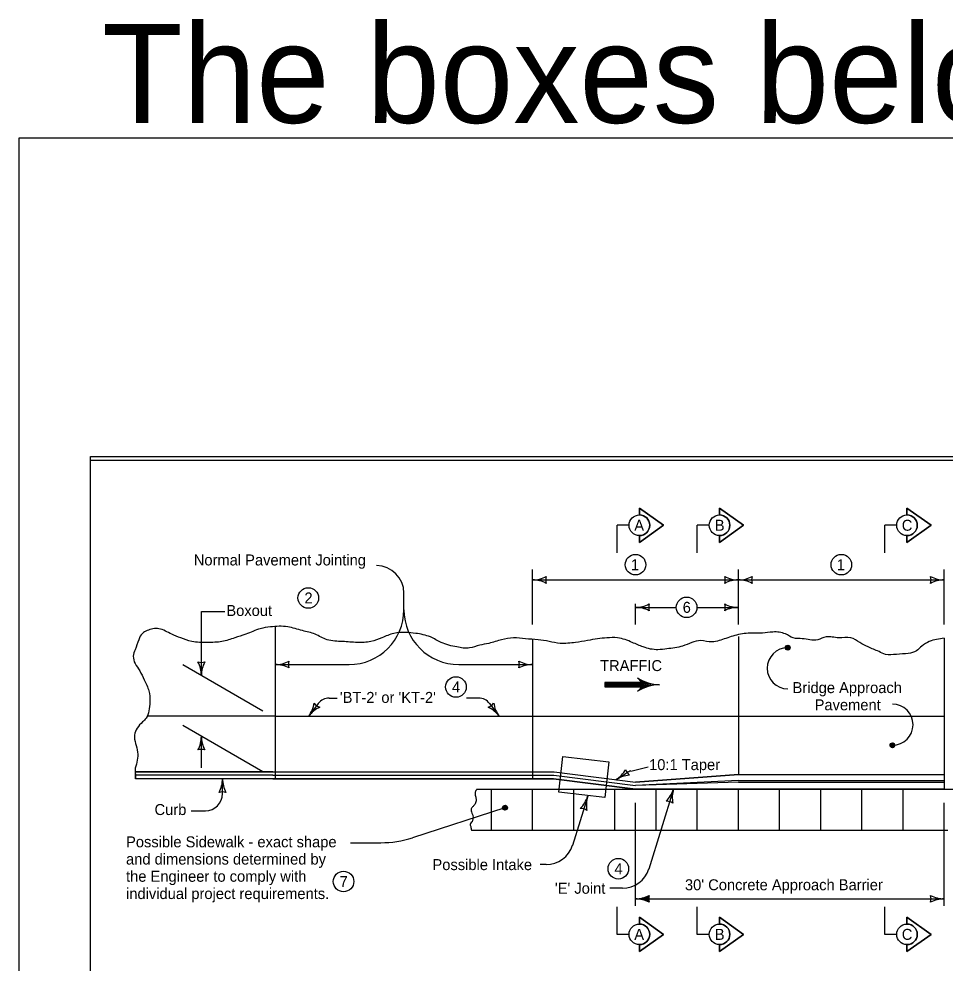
# Model space of a CAD drawing. Extents: x 10028 to 81668, y 6395 to 11634.
# Drawn here: x 10028 to 11378, y 9205 to 10582 of the extents above; entities that cross this region are included whole.
import ezdxf

# ---------------------------------------------------------------- set-up
doc = ezdxf.new("R2010")
doc.units = 0
for name, color, linetype in [('Default', 7, 'Continuous'), ('dsnCellElements', 7, 'Continuous'), ('dsnstdblockInterim', 7, 'Continuous'), ('dsnStdDimension', 7, 'Continuous'), ('dsnStdTextLabel', 7, 'Continuous'), ('ShtPlotIdentification', 7, 'Continuous')]:
    doc.layers.add(name, color=color, linetype=linetype)

msp = doc.modelspace()

# ---------------------------------------------------------------- linework, layer by layer
at = {"layer": 'Default'}
msp.add_lwpolyline([(10132.5, 9944), (13267.5, 9944), (13267.5, 7924), (10132.5, 7924)], close=True, dxfattribs=at)
msp.add_lwpolyline([(10132.5, 9944), (13267.5, 9944), (13267.5, 7924), (10132.5, 7924)], close=True, dxfattribs=at)
at = {"layer": 'dsnCellElements'}
for p, q in [((10932.4, 9828.9), (10932.4, 9828.9)), ((11049.2, 9828.9), (11049.2, 9828.9)), ((11322.4, 9828.9), (11322.4, 9828.9)), ((10198.2, 9474.3), (10197.8, 9484.3)), ((10197.8, 9484.3), (10398.2, 9484.3)), ((10398.2, 9474.3), (10198.2, 9474.3)), ((10926.7, 9469.3), (11076.7, 9480.5)), ((11076.7, 9480.5), (11376.7, 9480.5)), ((11376.7, 9480.5), (11376.7, 9459.2)), ((11376.7, 9459.2), (10926.7, 9459.2)), ((10932.4, 9232.4), (10932.4, 9232.4)), ((11049.2, 9232.4), (11049.2, 9232.4)), ((11322.4, 9232.4), (11322.4, 9232.4))]:
    msp.add_line(p, q, dxfattribs=at)
for points in [[(10932.4, 9828.9), (10932.4, 9818.9), (10967.4, 9843.9), (10932.4, 9868.9), (10932.4, 9858.9)], [(11049.2, 9828.9), (11049.2, 9818.9), (11084.2, 9843.9), (11049.2, 9868.9), (11049.2, 9858.9)], [(11322.4, 9828.9), (11322.4, 9818.9), (11357.4, 9843.9), (11322.4, 9868.9), (11322.4, 9858.9)], [(10398.2, 9484.3), (10808.3, 9484.3), (10926.7, 9469.3)], [(10926.7, 9459.2), (10807.2, 9474.3), (10398.2, 9474.3)], [(10932.4, 9232.4), (10932.4, 9222.4), (10967.4, 9247.4), (10932.4, 9272.4), (10932.4, 9262.4)], [(11049.2, 9232.4), (11049.2, 9222.4), (11084.2, 9247.4), (11049.2, 9272.4), (11049.2, 9262.4)], [(11322.4, 9232.4), (11322.4, 9222.4), (11357.4, 9247.4), (11322.4, 9272.4), (11322.4, 9262.4)]]:
    msp.add_lwpolyline(points, dxfattribs=at)
for centre in [(10932.4, 9843.9), (11049.2, 9843.9), (11322.4, 9843.9), (10932.4, 9247.4), (11049.2, 9247.4), (11322.4, 9247.4)]:
    msp.add_arc(centre, 15, 270.0001, 89.9999, dxfattribs=at)
at = {"layer": 'dsnstdblockInterim'}
for points in [[(10132.5, 9944), (13267.5, 9944), (13267.5, 7924), (10132.5, 7924)], [(10132.5, 9939), (13267.5, 9939), (13267.5, 7929), (10132.5, 7929)]]:
    msp.add_lwpolyline(points, close=True, dxfattribs=at)
at = {"layer": 'dsnStdDimension'}
msp.add_lwpolyline([(10028, 7824.5), (13372, 7824.5), (13372, 10408.5), (10028, 10408.5)], close=True, dxfattribs=at)
at = {"layer": 'ShtPlotIdentification'}
for p, q in [((10900, 9803.9), (10900, 9843.9)), ((10917.4, 9843.9), (10900, 9843.9)), ((11034.2, 9843.9), (11016.7, 9843.9)), ((11016.7, 9803.9), (11016.7, 9843.9)), ((11290, 9803.9), (11290, 9843.9)), ((11307.4, 9843.9), (11290, 9843.9)), ((10776.7, 9699.2), (10776.7, 9779.2)), ((11076.7, 9699.2), (11076.7, 9779.2)), ((11376.7, 9699.2), (11376.7, 9779.2)), ((10776.7, 9764.2), (11076.7, 9764.2)), ((11076.7, 9764.2), (11376.7, 9764.2)), ((10589.2, 9720.8), (10589.2, 9745)), ((10926.7, 9699.2), (10926.7, 9729.2)), ((10926.7, 9724.2), (10986.2, 9724.2)), ((11016.2, 9724.2), (11076.7, 9724.2)), ((10294, 9718.4), (10328.2, 9718.4)), ((10294, 9624.8), (10294, 9718.4)), ((10401.7, 9696.3), (10401.7, 9474.3)), ((11076.7, 9681.6), (11076.7, 9480.5)), ((11376.7, 9679.2), (11376.7, 9459.2)), ((10776.7, 9677.8), (10776.7, 9474.3)), ((10383.7, 9573), (10266.8, 9640.5)), ((10401.7, 9640.8), (10509.2, 9640.8)), ((10669.2, 9640.8), (10776.7, 9640.8)), ((10934.9, 9611.5), (10881.8, 9611.5)), ((10934.7, 9614.7), (10934.7, 9614.7)), ((10934.8, 9608.5), (10934.8, 9608.5)), ((10464.3, 9583.9), (10450.4, 9565.5)), ((10480.3, 9591.9), (10492, 9591.9)), ((10698.1, 9591.9), (10680.5, 9591.9)), ((10714.1, 9583.9), (10728, 9565.5)), ((10401.7, 9565.5), (10215.1, 9565.5)), ((10401.7, 9565.5), (10776.7, 9565.5)), ((10776.7, 9565.5), (11376.7, 9565.5)), ((10383.7, 9484.5), (10266.8, 9552)), ((10294, 9490), (10294, 9536.3)), ((10197.6, 9489.5), (10198.2, 9474.3)), ((10920, 9485.6), (10945.2, 9491.6)), ((10398.2, 9484.3), (10197.8, 9484.3)), ((10398.2, 9479.3), (10198, 9479.3)), ((10398.2, 9474.3), (10198.2, 9474.3)), ((10324.8, 9452.6), (10324.8, 9474.3)), ((10898.3, 9472.9), (10913.8, 9483)), ((11076.7, 9480.5), (10926.7, 9469.3)), ((11076.7, 9480.5), (11376.7, 9480.5)), ((10695.6, 9459.2), (11376.7, 9459.2)), ((10716.7, 9399.2), (10716.7, 9459.2)), ((10776.7, 9399.2), (10776.7, 9459.2)), ((10836.7, 9399.2), (10836.7, 9459.2)), ((10896.7, 9399.2), (10896.7, 9459.2)), ((11076.7, 9471.7), (10926.7, 9464.3)), ((11076.7, 9469.2), (10926.7, 9464.3)), ((10926.7, 9459.2), (11376.7, 9459.2)), ((10926.7, 9459.2), (11367.8, 9459.2)), ((10982.2, 9459.2), (10946, 9342.7)), ((10956.7, 9399.2), (10956.7, 9459.2)), ((11016.7, 9399.2), (11016.7, 9459.2)), ((11076.7, 9471.7), (11376.7, 9471.7)), ((11076.7, 9469.2), (11376.7, 9469.2)), ((11076.7, 9399.2), (11076.7, 9459.2)), ((11136.7, 9399.2), (11136.7, 9459.2)), ((11196.7, 9399.2), (11196.7, 9459.2)), ((11256.7, 9399.2), (11256.7, 9459.2)), ((11316.7, 9399.2), (11316.7, 9459.2)), ((11376.7, 9459.2), (11706.6, 9459.2)), ((10857, 9448.7), (10834.8, 9377.2)), ((10736.5, 9432), (10601.8, 9388.3)), ((10926.7, 9289.2), (10926.7, 9439.2)), ((11376.7, 9289.2), (11376.7, 9439.2)), ((10278.9, 9427.6), (10299.8, 9427.6)), ((10687.5, 9399.2), (11381.7, 9399.2)), ((10511.5, 9381), (10555.5, 9381)), ((10796.6, 9349.1), (10788, 9349.1)), ((10907.8, 9314.6), (10889.4, 9314.6)), ((10926.7, 9299.2), (11376.7, 9299.2)), ((10926.7, 9299.2), (10945.9, 9299.2)), ((10900, 9247.4), (10900, 9287.4)), ((11016.7, 9247.4), (11016.7, 9287.4)), ((11290, 9247.4), (11290, 9287.4)), ((10917.4, 9247.4), (10900, 9247.4)), ((11034.2, 9247.4), (11016.7, 9247.4)), ((11307.4, 9247.4), (11290, 9247.4))]:
    msp.add_line(p, q, dxfattribs=at)
for points in [[(10932.4, 9858.9), (10932.4, 9868.9), (10967.4, 9843.9), (10932.4, 9818.9), (10932.4, 9828.9)], [(11049.2, 9858.9), (11049.2, 9868.9), (11084.2, 9843.9), (11049.2, 9818.9), (11049.2, 9828.9)], [(11322.4, 9858.9), (11322.4, 9868.9), (11357.4, 9843.9), (11322.4, 9818.9), (11322.4, 9828.9)], [(11148.4, 9662.2), (11149.5, 9662.8), (11151.4, 9663.3), (11151.7, 9665.2), (11151.5, 9666.8), (11150.3, 9668.3), (11148.6, 9668.2), (11146.7, 9667.9), (11145.8, 9666.5), (11145.7, 9664.9), (11146.8, 9662.9), (11148.1, 9662.7), (11149.9, 9663.2), (11151.4, 9664.4), (11151.4, 9666.1), (11150.2, 9667.5), (11148.6, 9667.7), (11146.7, 9667.3), (11146.4, 9666.3), (11146.1, 9665), (11146.9, 9663.5), (11148.3, 9663.5), (11149.8, 9663.8), (11150.9, 9664.6), (11150.4, 9666.2), (11149.2, 9667.1), (11147.7, 9667.1), (11147.3, 9666.3), (11146.8, 9665.4), (11147.5, 9664.1), (11148.7, 9663.9), (11149.7, 9664.4), (11149.8, 9665.5), (11149.2, 9666.3), (11148.2, 9666.6), (11147.7, 9666.2), (11147.4, 9665.6), (11147.9, 9664.7), (11148.7, 9664.5), (11149.4, 9664.9), (11149.3, 9665.5), (11148.7, 9665.9), (11148, 9665.9), (11148, 9665.4), (11148.6, 9665.1)], [(10934.8, 9614.5), (10881.8, 9614.5), (10881.8, 9608.5), (10934.8, 9608.5), (10934.6, 9613.6), (10882.5, 9613.8), (10882.6, 9609), (10933.6, 9609.2), (10933.7, 9612.8), (10883.2, 9613), (10883.4, 9609.8), (10932.9, 9609.8), (10933.1, 9612.1), (10883.8, 9612.4), (10883.9, 9610.6), (10932.3, 9610.6)], [(10933.3, 9618.4), (10935.6, 9614.8), (10935.9, 9609.6), (10933.9, 9605), (10941.8, 9608.3), (10950.9, 9610.9), (10953.5, 9611.5), (10946.9, 9612.8), (10937.2, 9616.1), (10934.4, 9617.7), (10935.5, 9606.5), (10949.6, 9611.3), (10935.8, 9615.5), (10936.3, 9607.8), (10946, 9611.4), (10937.1, 9613.6), (10936.7, 9609.1), (10942.9, 9611.1), (10938.2, 9612.4), (10937.9, 9610.3), (10940.2, 9611)], [(11300.9, 9519.9), (11302.1, 9520.4), (11303.9, 9521), (11304.3, 9522.9), (11304, 9524.5), (11302.9, 9526), (11301.1, 9525.9), (11299.3, 9525.6), (11298.4, 9524.1), (11298.2, 9522.6), (11299.3, 9520.6), (11300.7, 9520.4), (11302.5, 9520.9), (11304, 9522), (11304, 9523.8), (11302.8, 9525.2), (11301.1, 9525.4), (11299.3, 9525), (11299, 9524), (11298.6, 9522.7), (11299.5, 9521.2), (11300.8, 9521.2), (11302.4, 9521.5), (11303.5, 9522.3), (11302.9, 9523.9), (11301.8, 9524.8), (11300.2, 9524.8), (11299.8, 9524), (11299.4, 9523), (11300.1, 9521.8), (11301.2, 9521.6), (11302.3, 9522.1), (11302.3, 9523.2), (11301.8, 9524), (11300.8, 9524.3), (11300.3, 9523.9), (11300, 9523.3), (11300.5, 9522.4), (11301.2, 9522.2), (11301.9, 9522.6), (11301.8, 9523.2), (11301.3, 9523.6), (11300.6, 9523.6), (11300.6, 9523.1), (11301.2, 9522.8)], [(10398.2, 9484.3), (10808.3, 9484.3), (10926.7, 9469.3)], [(10398.2, 9479.3), (10807.7, 9479.3), (10926.7, 9464.3)], [(10398.2, 9474.3), (10807.2, 9474.3), (10926.7, 9459.2)], [(10737.2, 9428.9), (10738.2, 9429.8), (10739.7, 9430.9), (10739.5, 9432.8), (10738.7, 9434.2), (10737.2, 9435.3), (10735.5, 9434.6), (10733.9, 9433.8), (10733.5, 9432.2), (10733.8, 9430.6), (10735.5, 9429), (10736.8, 9429.3), (10738.4, 9430.3), (10739.5, 9431.9), (10738.9, 9433.5), (10737.3, 9434.5), (10735.7, 9434.1), (10734.1, 9433.2), (10734.1, 9432.2), (10734.2, 9430.9), (10735.5, 9429.7), (10736.7, 9430.1), (10738.1, 9430.8), (10738.9, 9432), (10737.9, 9433.3), (10736.5, 9433.8), (10735, 9433.4), (10734.9, 9432.4), (10734.7, 9431.4), (10735.8, 9430.5), (10737, 9430.6), (10737.8, 9431.4), (10737.5, 9432.5), (10736.7, 9433.1), (10735.7, 9433), (10735.3, 9432.5), (10735.2, 9431.8), (10736, 9431.1), (10736.8, 9431.1), (10737.3, 9431.8), (10737, 9432.3), (10736.4, 9432.5), (10735.7, 9432.3), (10735.9, 9431.8), (10736.6, 9431.7)], [(10737.2, 9428.9), (10738.2, 9429.8), (10739.7, 9430.9), (10739.5, 9432.8), (10738.7, 9434.2), (10737.2, 9435.3), (10735.5, 9434.6), (10733.9, 9433.8), (10733.5, 9432.2), (10733.8, 9430.6), (10735.5, 9429), (10736.8, 9429.3), (10738.4, 9430.3), (10739.5, 9431.9), (10738.9, 9433.5), (10737.3, 9434.5), (10735.7, 9434.1), (10734.1, 9433.2), (10734.1, 9432.2), (10734.2, 9430.9), (10735.5, 9429.7), (10736.7, 9430.1), (10738.1, 9430.8), (10738.9, 9432), (10737.9, 9433.3), (10736.5, 9433.8), (10735, 9433.4), (10734.9, 9432.4), (10734.7, 9431.4), (10735.8, 9430.5), (10737, 9430.6), (10737.8, 9431.4), (10737.5, 9432.5), (10736.7, 9433.1), (10735.7, 9433), (10735.3, 9432.5), (10735.2, 9431.8), (10736, 9431.1), (10736.8, 9431.1), (10737.3, 9431.8), (10737, 9432.3), (10736.4, 9432.5), (10735.7, 9432.3), (10735.9, 9431.8), (10736.6, 9431.7)], [(10945.5, 9295.7), (10944.8, 9299.2), (10945.6, 9302.9), (10941.3, 9300.8), (10934.4, 9299.2), (10941.8, 9297.5), (10944.9, 9296.1), (10944.1, 9299.2), (10944.4, 9301.6), (10941.6, 9300.2), (10937.8, 9299.2), (10941.9, 9298.1), (10944, 9297.4), (10943.6, 9300.4), (10940.8, 9299.2), (10943, 9298.6), (10943, 9299.6), (10942, 9299.3)], [(10932.4, 9262.4), (10932.4, 9272.4), (10967.4, 9247.4), (10932.4, 9222.4), (10932.4, 9232.4)], [(11049.2, 9262.4), (11049.2, 9272.4), (11084.2, 9247.4), (11049.2, 9222.4), (11049.2, 9232.4)], [(11322.4, 9262.4), (11322.4, 9272.4), (11357.4, 9247.4), (11322.4, 9222.4), (11322.4, 9232.4)]]:
    msp.add_lwpolyline(points, dxfattribs=at)
msp.add_lwpolyline([(10814.9, 9454.7), (10820.9, 9506.9), (10887.9, 9499.2), (10882, 9447.1)], close=True, dxfattribs=at)
for centre, radius in [((10932.4, 9843.9), 15), ((11049.2, 9843.9), 15), ((11322.4, 9843.9), 15), ((10926.7, 9786.4), 15), ((11226.7, 9786.4), 15), ((10449.8, 9737.9), 15), ((11001.2, 9724.2), 15), ((11148.6, 9665.4), 3.5), ((10665, 9608.1), 15), ((11301.2, 9523.1), 3.5), ((10736.5, 9432), 3.5), ((10736.5, 9432), 3.5), ((10901.7, 9343.1), 15), ((10501.2, 9324.5), 15), ((10932.4, 9247.4), 15), ((11049.2, 9247.4), 15), ((11322.4, 9247.4), 15)]:
    msp.add_circle(centre, radius, dxfattribs=at)
for centre, radius, start, end in [((10549.2, 9745), 40, 0, 90), ((10776.7, 9806.7), 42.5, 270, 298.0725), ((10776.7, 9721.7), 42.5, 61.9275, 90), ((10812.3, 9764.2), 16.4, 162.2666, 197.7334), ((11041.1, 9764.2), 16.4, 342.2666, 17.7333), ((11076.7, 9806.7), 42.5, 241.9275, 270), ((11041.1, 9764.2), 16.4, 342.2666, 17.7333), ((11076.7, 9806.7), 42.5, 241.9275, 270), ((11076.7, 9721.7), 42.5, 90, 118.0725), ((11076.7, 9721.7), 42.5, 90, 118.0725), ((11076.7, 9806.7), 42.5, 270, 298.0725), ((11076.7, 9721.7), 42.5, 61.9275, 90), ((11112.3, 9764.2), 16.4, 162.2666, 197.7334), ((11341.1, 9764.2), 16.4, 342.2666, 17.7333), ((11376.7, 9806.7), 42.5, 241.9275, 270), ((11376.7, 9721.7), 42.5, 90, 118.0725), ((10509.2, 9720.8), 80, 270, 360), ((10669.2, 9720.8), 80, 180, 270), ((10926.7, 9766.7), 42.5, 270, 298.0725), ((10926.7, 9766.7), 42.5, 270, 298.0725), ((10926.7, 9681.7), 42.5, 61.9275, 90), ((10926.7, 9681.7), 42.5, 61.9275, 90), ((10962.3, 9724.2), 16.4, 162.2666, 197.7334), ((10962.3, 9724.2), 16.4, 162.2666, 197.7334), ((11041.1, 9724.2), 16.4, 342.2666, 17.7333), ((11076.7, 9766.7), 42.5, 241.9275, 270), ((11041.1, 9724.2), 16.4, 342.2666, 17.7333), ((11076.7, 9766.7), 42.5, 241.9275, 270), ((11076.7, 9681.7), 42.5, 90, 118.0725), ((11076.7, 9681.7), 42.5, 90, 118.0725), ((11148.6, 9635.4), 30, 90, 270), ((10294, 9660.4), 16.4, 252.2666, 287.7333), ((10251.5, 9624.8), 42.5, 360, 28.0725), ((10294, 9660.4), 16.4, 252.2666, 287.7333), ((10251.5, 9624.8), 42.5, 360, 28.0725), ((10336.5, 9624.8), 42.5, 151.9275, 180), ((10336.5, 9624.8), 42.5, 151.9275, 180), ((10401.7, 9683.3), 42.5, 270, 298.0725), ((10401.7, 9598.3), 42.5, 61.9275, 90), ((10437.3, 9640.8), 16.4, 162.2666, 197.7334), ((10741.1, 9640.8), 16.4, 342.2666, 17.7333), ((10776.7, 9683.3), 42.5, 241.9275, 270), ((10776.7, 9598.3), 42.5, 90, 118.0725), ((10923.9, 9611.5), 11.3, 301.7147, 58.2853), ((10963.7, 9675.9), 64.5, 238.2857, 268.3158), ((10963.7, 9547), 64.5, 91.6842, 121.7143), ((10416.4, 9591), 42.5, 323.1296, 351.2021), ((10416.4, 9591), 42.5, 323.1296, 351.2021), ((10471.8, 9594), 16.4, 215.3963, 250.863), ((10471.8, 9594), 16.4, 215.3963, 250.863), ((10480.3, 9571.9), 20, 90, 143.1298), ((10698.1, 9571.9), 20, 36.8702, 90), ((10706.6, 9594), 16.4, 289.137, 324.6037), ((10762, 9591), 42.5, 188.7979, 216.8704), ((11301.2, 9553.1), 30, 270, 90), ((10484.4, 9540), 42.5, 115.0571, 143.1296), ((10484.4, 9540), 42.5, 115.0571, 143.1296), ((10694, 9540), 42.5, 36.8704, 64.9429), ((10251.5, 9536.3), 42.5, 331.9275, 360), ((10251.5, 9536.3), 42.5, 331.9275, 360), ((10336.5, 9536.3), 42.5, 180, 208.0725), ((10336.5, 9536.3), 42.5, 180, 208.0725), ((10294, 9500.7), 16.4, 72.2666, 107.7334), ((10294, 9500.7), 16.4, 72.2666, 107.7334), ((10875.2, 9508.6), 42.5, 302.8813, 330.9538), ((10928.2, 9492.2), 16.4, 195.1479, 230.6146), ((10282.3, 9474.3), 42.5, 331.9275, 360), ((10282.3, 9474.3), 42.5, 331.9275, 360), ((10367.3, 9474.3), 42.5, 180, 208.0725), ((10367.3, 9474.3), 42.5, 180, 208.0725), ((10921.3, 9437.2), 42.5, 94.8088, 122.8813), ((10924.7, 9466.2), 20, 103.3899, 122.8807), ((10941.6, 9471.8), 42.5, 314.6617, 342.7342), ((10941.6, 9471.8), 42.5, 314.6617, 342.7342), ((11022.8, 9446.6), 42.5, 162.7342, 190.8067), ((11022.8, 9446.6), 42.5, 162.7342, 190.8067), ((10299.8, 9452.6), 25, 270, 360), ((10324.8, 9438.6), 16.4, 72.2666, 107.7334), ((10324.8, 9438.6), 16.4, 72.2666, 107.7334), ((10816.4, 9461.3), 42.5, 314.6616, 342.7341), ((10897.6, 9436.1), 42.5, 162.7341, 190.8065), ((10846.4, 9414.7), 16.4, 55.0007, 90.4674), ((10971.6, 9425.2), 16.4, 55.0008, 90.4675), ((10971.6, 9425.2), 16.4, 55.0008, 90.4675), ((10555.5, 9531), 150, 270, 287.9785), ((10796.6, 9389.1), 40, 270, 342.7338), ((10907.8, 9354.6), 40, 270, 342.7338), ((10926.7, 9341.7), 42.5, 270, 298.0725), ((10926.7, 9256.7), 42.5, 61.9275, 90), ((10962.3, 9299.2), 16.4, 162.2666, 197.7334), ((11341.1, 9299.2), 16.4, 342.2666, 17.7333), ((11376.7, 9341.7), 42.5, 241.9275, 270), ((11376.7, 9256.7), 42.5, 90, 118.0725)]:
    msp.add_arc(centre, radius, start, end, dxfattribs=at)
for points in [[(11376.7, 9679.2), (11354.9, 9674.4), (11344.2, 9667.7), (11336.3, 9661), (11324.3, 9657), (11307, 9655.7), (11291, 9655.7), (11281.6, 9659.7), (11265.7, 9666.4), (11253.7, 9673), (11240.4, 9679.7), (11223, 9679.7), (11204.4, 9681), (11192.4, 9677), (11181, 9676.8), (11169.8, 9678.4), (11156.7, 9679.6), (11145.3, 9685.4), (11126.8, 9688.2), (11111.9, 9686.6), (11091, 9686.4), (11068.5, 9682.3), (11048.6, 9675.7), (11038.2, 9673.7), (11021.9, 9675.7), (11008.6, 9673), (10995.3, 9667.7), (10972.6, 9663.7), (10959.3, 9662.4), (10938, 9666.4), (10922, 9673), (10900.7, 9679.7), (10884.7, 9679.7), (10871.4, 9678.4), (10856.8, 9675.7), (10839.4, 9673), (10816.8, 9671.7), (10800.8, 9674.4), (10784.8, 9677), (10766.2, 9678.4), (10748.9, 9679.7), (10731.6, 9677), (10712.9, 9671.7), (10699.6, 9669), (10684.9, 9665), (10666.3, 9666.4), (10643.6, 9673), (10627.7, 9681), (10606.4, 9686.3), (10591.7, 9687.7), (10574.4, 9686.3), (10557.1, 9679.7), (10541.1, 9674.4), (10521.1, 9673), (10499.8, 9674.4), (10477.2, 9677), (10459.8, 9685), (10441.2, 9690.3), (10419.9, 9695.7), (10394.6, 9695.7), (10379.9, 9693), (10358.6, 9685), (10342.6, 9679.7), (10324, 9674.4), (10302.7, 9673), (10280, 9674.4), (10264, 9679.7), (10250.7, 9685), (10232.1, 9693), (10214.8, 9690.3), (10208.1, 9686.3), (10202.8, 9677), (10197.4, 9662.4), (10194.8, 9653), (10197.4, 9642.4), (10204.1, 9631.7), (10210.8, 9618.4), (10217.4, 9602.4), (10218.8, 9586.4), (10217.4, 9573.1), (10213.4, 9562.5), (10208.1, 9557.1), (10196.5, 9537.9), (10201.1, 9513.2), (10197.6, 9489.5)], [(10695.6, 9459.2), (10693.1, 9454.7), (10693.6, 9448.7), (10694.5, 9443.7), (10693.1, 9437.9), (10689.9, 9434), (10687.4, 9430.6), (10688.1, 9424.3), (10689.7, 9420.2), (10689.7, 9415.8), (10688.5, 9411.7), (10686, 9408.9), (10686.5, 9404.6), (10687.5, 9399.2)]]:
    msp.add_spline(points, degree=3, dxfattribs=at)

# ---------------------------------------------------------------- texts
at = {"layer": 'dsnCellElements'}
for s, p in [('A', (10924.9, 9835.9)), ('B', (11042.3, 9835.9)), ('C', (11314.8, 9835.9)), ('Normal Pavement Jointing', (10282.9, 9785.3)), ('1', (10920.1, 9778.4)), ('1', (11220.1, 9778.4)), ('2', (10444.2, 9729.9)), ('Boxout', (10330.4, 9711.6)), ('6', (10995.5, 9716.2)), ('TRAFFIC', (10875.1, 9631.3)), ('4', (10659.3, 9600.1)), ('Bridge Approach', (11155.6, 9599.2)), ("'BT-2' or 'KT-2'", (10495.8, 9584.9)), ('Pavement', (11187.8, 9574.1)), ('Curb', (10225.7, 9421.4)), ('Possible Sidewalk - exact shape ', (10184.2, 9374.3)), ('and dimensions determined by ', (10184.2, 9349.2)), ('Possible Intake', (10630.8, 9341.1)), ('4', (10896, 9335.1)), ('the Engineer to comply with ', (10184.2, 9324.1)), ("'E' Joint", (10809.2, 9306.6)), ("30' Concrete Approach Barrier", (10998.8, 9311.7)), ('individual project requirements.', (10184.2, 9298.9)), ('A', (10924.9, 9239.4)), ('B', (11042.3, 9239.4)), ('C', (11314.8, 9239.4))]:
    msp.add_text(s, height=16, dxfattribs=at).set_placement(p)
msp.add_text('10:1 Taper', height=16, rotation=360, dxfattribs=at).set_placement((10946.5, 9486.9))
at = {"layer": 'dsnStdTextLabel'}
msp.add_text('The boxes below encompass the usable area within the print border.', height=144, dxfattribs=at).set_placement((10149.1, 10430.6))
at = {"layer": 'ShtPlotIdentification'}
msp.add_text('7', height=16, dxfattribs=at).set_placement((10495.5, 9316.5))

doc.saveas('drawing.dxf')
